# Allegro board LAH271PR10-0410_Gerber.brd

Outline 372.25 x 154.5 mm; copper layers: TOP, GND1, IN1, GND2, IN2, GND3, VCC, IN3, GND4, IN4, GND5, BOTTOM. Coordinates in mm from the lower left corner of the outline.
Outline path: 0,69.3 0,67.85 arc(0.02,67.72) 0.07,67.6 0.43,66.97 arc(0.48,66.85) 0.5,66.72 0.5,59.98 arc(0.48,59.85) 0.43,59.73 0.07,59.1 arc(0.02,58.98) 0,58.85 0,58.05 arc(0.15,57.7) 0.5,57.55 1,57.55 arc(1.5,57.05) 1,56.55 1,53.95 arc(1.5,53.45) 1,52.95 0.5,52.95 arc(0.15,52.8) 0,52.45 0,51.65 arc(0.02,51.52) 0.07,51.4 0.43,50.77 arc(0.48,50.65) 0.5,50.52 0.5,43.78 arc(0.48,43.65) 0.43,43.53 0.07,42.9 arc(0.02,42.78) 0,42.65 0,41.2 1.55,41.2 arc(2.05,40.7) 1.55,40.2 1.55,36.35 1.85,36.35 arc(2.2,36.2) 2.35,35.85 2.35,5.85 arc(2.7,5.7) 2.85,5.35 2.85,0 343.05,0 343.05,5.56 arc(343.42,6.04) 343.98,5.81 arc(344.17,5.62) 344.42,5.56 362.88,5.56 arc(363.13,5.62) 363.32,5.81 arc(363.88,6.04) 364.25,5.56 364.25,0 370.95,0 370.95,1.65 368.9,1.65 arc(367.65,2.9) 368.9,4.15 370.95,4.15 370.95,10.3 arc(371.1,10.65) 371.45,10.8 371.65,10.8 371.65,13.9 371.45,13.9 arc(371.1,14.05) 370.95,14.4 370.95,19.4 arc(371.1,19.75) 371.45,19.9 371.65,19.9 371.65,23 371.45,23 arc(371.1,23.15) 370.95,23.5 370.95,27.8 368.02,27.8 arc(367.52,28.3) 368.02,28.8 368.02,35.8 arc(367.52,36.3) 368.02,36.8 370.95,36.8 370.95,49.8 368.02,49.8 arc(367.52,50.3) 368.02,50.8 368.02,57.8 arc(367.52,58.3) 368.02,58.8 370.95,58.8 370.95,67.5 arc(371.1,67.85) 371.45,68 371.75,68 arc(372.1,68.15) 372.25,68.5 372.25,73.65 arc(372.1,74) 371.75,74.15 361.75,74.15 arc(359.6,73.42) 358.36,71.52 356.68,67.46 354.6,64.28 351.93,61.53 348.42,58.85 arc(338.59,54.15) 327.8,52.7 324.63,52.7 arc(320.32,53.05) 316.08,53.89 arc(308.17,57.19) 301.52,62.6 arc(291.64,77.48) 286.89,94.71 281.32,145.2 274.15,145.2 arc(273.8,145.35) 273.65,145.7 273.65,153 272.15,154.5 241.05,154.5 239.65,153.1 239.65,152.05 arc(239.5,151.7) 239.15,151.55 233.65,151.55 230.7,154.5 217.44,154.5 217.44,144.96 arc(217.3,144.61) 216.94,144.46 215.04,144.46 arc(214.69,144.31) 214.54,143.96 214.54,143.61 arc(214.4,143.26) 214.04,143.11 204.24,143.11 arc(203.89,143.26) 203.74,143.61 203.74,143.96 arc(203.6,144.31) 203.24,144.46 201.34,144.46 arc(200.99,144.61) 200.84,144.96 200.84,154.5 171.45,154.5 171.45,152.05 arc(171.3,151.7) 170.95,151.55 168.45,151.55 168.45,65.5 154.85,51.9 132.4,51.9 arc(132.05,51.75) 131.9,51.4 arc(131.75,51.05) 131.4,50.9 118.15,50.9 arc(117.8,51.05) 117.65,51.4 arc(117.5,51.75) 117.15,51.9 85.45,51.9 arc(85.1,52.05) 84.95,52.4 84.95,64.9 arc(84.66,65.61) 83.95,65.9 75.66,65.9 arc(75.1,65.73) 74.73,65.27 arc(71.94,60.64) 67.78,57.17 arc(66.51,55.89) 66.05,54.15 66.05,43.9 arc(65.9,43.55) 65.55,43.4 48.25,43.4 arc(47.9,43.55) 47.75,43.9 47.75,50.7 arc(47.16,52.11) 45.75,52.7 44.71,52.7 arc(34.33,54.28) 24.88,58.86 21.42,61.5 18.69,64.31 16.55,67.6 14.89,71.71 arc(13.62,73.47) 11.55,74.15 1.55,74.15 1.55,70.3 arc(2.05,69.8) 1.55,69.3 0,69.3

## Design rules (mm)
net group CSS_1: nets CSSN_1 CSSP_1
net group DIFFPAIR127: nets VCC_SA_SENSE VSS_SA_SENSE
net group DIFFPAIR128: nets VCC_SENSE VSS_SENSE
net group DIFFPAIR129: nets VCC_GT_SENSE VSS_GT_SENSE
net group DIFFPAIR130: nets CSSN_2 CSSP_2
net group DIFFPAIR152: nets SW4_DP2_N2 SW4_DP2_P2
net group DIFFPAIR153: nets SW4_DP2_N1 SW4_DP2_P1
net group DIFFPAIR154: nets SW4_DP2_N0 SW4_DP2_P0
net group DIFFPAIR155: nets PCIE_PRX_C_TTX_N4 PCIE_PRX_C_TTX_P4
net group DIFFPAIR156: nets PCIE_PRX_TTX_N4 PCIE_PRX_TTX_P4
net group DIFFPAIR159: nets PCIE_PRX_C_TTX_N3 PCIE_PRX_C_TTX_P3
net group DIFFPAIR160: nets PCIE_PRX_TTX_N3 PCIE_PRX_TTX_P3
net group DIFFPAIR163: nets PCIE_PRX_C_TTX_N2 PCIE_PRX_C_TTX_P2
net group DIFFPAIR164: nets PCIE_PRX_TTX_N2 PCIE_PRX_TTX_P2
net group DIFFPAIR167: nets PCIE_PRX_C_TTX_N1 PCIE_PRX_C_TTX_P1
net group DIFFPAIR168: nets PCIE_PRX_TTX_N1 PCIE_PRX_TTX_P1
net group DIFFPAIR171: nets SW3_DP1_AUXN SW3_DP1_AUXP
net group DIFFPAIR172: nets SW3_DP1_AUXN_C SW3_DP1_AUXP_C
net group DIFFPAIR173: nets SW4_DP2_AUXN SW4_DP2_AUXP
net group DIFFPAIR174: nets SW4_DP2_AUXN_C SW4_DP2_AUXP_C
net group DIFFPAIR175: nets SW3_DP1_N0_C SW3_DP1_P0_C
net group DIFFPAIR176: nets SW3_DP1_N0 SW3_DP1_P0
net group DIFFPAIR177: nets SW3_DP1_N1_C SW3_DP1_P1_C
net group DIFFPAIR178: nets SW3_DP1_N1 SW3_DP1_P1
net group DIFFPAIR179: nets SW3_DP1_N2_C SW3_DP1_P2_C
net group DIFFPAIR180: nets SW3_DP1_N2 SW3_DP1_P2
net group DIFFPAIR181: nets SW3_DP1_N3_C SW3_DP1_P3_C
net group DIFFPAIR182: nets SW3_DP1_N3 SW3_DP1_P3
net group DIFFPAIR191: nets USB20_NB USB20_PB
net group DIFFPAIR192: nets SW4_DP2_N3 SW4_DP2_P3
net group DIFFPAIR224: nets GPU_DP2_N0 GPU_DP2_P0
net group DIFFPAIR225: nets GPU_DP2_N3 GPU_DP2_P3
net group DIFFPAIR226: nets GPU_DP2_N1 GPU_DP2_P1
net group DIFFPAIR227: nets GPU_DP2_N2 GPU_DP2_P2
net group DIFFPAIR238: nets PCH_DPC_CTRL_CLK PCH_DPC_CTRL_DATA
net group DIFFPAIR239: nets SML0_SMBCLK SML0_SMBDATA
net group DIFFPAIR240: nets PCH_CL_CLK1 PCH_CL_DATA1
net group DIFFPAIR245: nets SD_1_CMD_R SD_1_D3_R
net group DIFFPAIR246: nets GPU_SMCLK GPU_SMDAT
net group DIFFPAIR252: nets TBT_B_TRX_DTX_N2_R TBT_B_TRX_DTX_P2_R
net group DIFFPAIR253: nets TBT_B_TRX_DTX_N1_R TBT_B_TRX_DTX_P1_R
net group DIFFPAIR254: nets SW_TBT_A_USB20_N2_R SW_TBT_A_USB20_P2_R
net group DIFFPAIR256: nets TBTA_DPSRC_AUX_N_C TBTA_DPSRC_AUX_P_C
net group DIFFPAIR261: nets TBT_A_TTX_DRX_N1_R TBT_A_TTX_DRX_P1_R
net group DIFFPAIR262: nets TBT_A_TTX_DRX_N2_R TBT_A_TTX_DRX_P2_R
net group DIFFPAIR263: nets TBT_B_TTX_DRX_N1_R TBT_B_TTX_DRX_P1_R
net group DIFFPAIR264: nets DMIC0 DMIC_CLK
net group DIFFPAIR265: nets TBT_B_TTX_DRX_N2_R TBT_B_TTX_DRX_P2_R
net group S18: nets PCH_PECI PECI_EC_R
net group S25: nets VCC_IO_SENSE VSS_IO_SENSE
net group USB3_TX: nets USB3_PRX_L_DTX_N2 USB3_PRX_L_DTX_P2
net group 1111: nets DDR_A_ACT# DDR_A_BA0 DDR_A_BA1 DDR_A_BG0 DDR_A_BG1 DDR_A_CB0 DDR_A_CB1 DDR_A_CB2 DDR_A_CB3 DDR_A_CB4 DDR_A_CB5 DDR_A_CB6 DDR_A_CB7 DDR_A_CKE0 DDR_A_CKE1 DDR_A_CKE2 DDR_A_CKE3 DDR_A_CLK0 DDR_A_CLK1 DDR_A_CLK2 DDR_A_CLK3 DDR_A_CLK#0 DDR_A_CLK#1 DDR_A_CLK#2 DDR_A_CLK#3 DDR_A_CS#0 DDR_A_CS#1 DDR_A_CS#2 DDR_A_CS#3 DDR_A_D0 DDR_A_D1 DDR_A_D2 DDR_A_D3 DDR_A_D4 DDR_A_D5 DDR_A_D6 DDR_A_D7 DDR_A_D8 DDR_A_D9 DDR_A_D10 DDR_A_D11 DDR_A_D12 DDR_A_D13 DDR_A_D14 DDR_A_D15 DDR_A_D16 DDR_A_D17 DDR_A_D18 DDR_A_D19 DDR_A_D20 DDR_A_D21 DDR_A_D22 DDR_A_D23 DDR_A_D24 DDR_A_D25 DDR_A_D26 DDR_A_D27 DDR_A_D28 DDR_A_D29 DDR_A_D30 DDR_A_D31 DDR_A_D32 DDR_A_D33 DDR_A_D34 DDR_A_D35 DDR_A_D36 DDR_A_D37 DDR_A_D38 DDR_A_D39 DDR_A_D40 DDR_A_D41 DDR_A_D42 DDR_A_D43 DDR_A_D44 DDR_A_D45 DDR_A_D46 DDR_A_D47 DDR_A_D48 DDR_A_D49 DDR_A_D50 DDR_A_D51 DDR_A_D52 DDR_A_D53 DDR_A_D54 DDR_A_D55 DDR_A_D56 DDR_A_D57 DDR_A_D58 DDR_A_D59 DDR_A_D60 DDR_A_D61 DDR_A_D62 DDR_A_D63 DDR_A_DQS0 DDR_A_DQS1 DDR_A_DQS2 DDR_A_DQS3 DDR_A_DQS4 DDR_A_DQS5 DDR_A_DQS6 DDR_A_DQS7 DDR_A_DQS8 DDR_A_DQS#0 DDR_A_DQS#1 DDR_A_DQS#2 DDR_A_DQS#3 DDR_A_DQS#4 DDR_A_DQS#5 DDR_A_DQS#6 DDR_A_DQS#7 DDR_A_DQS#8 DDR_A_MA0 DDR_A_MA1 DDR_A_MA2 DDR_A_MA3 DDR_A_MA4 DDR_A_MA5 DDR_A_MA6 DDR_A_MA7 DDR_A_MA8 DDR_A_MA9 DDR_A_MA10 DDR_A_MA11 DDR_A_MA12 DDR_A_MA13 DDR_A_MA14 DDR_A_MA15 DDR_A_MA16 DDR_A_ODT0 DDR_A_ODT1 DDR_A_ODT2 DDR_A_ODT3 DDR_A_PARITY DDR_B_ACT# DDR_B_BA0 DDR_B_BA1 DDR_B_BG0 DDR_B_BG1 DDR_B_CB0 DDR_B_CB1 DDR_B_CB2 DDR_B_CB3 DDR_B_CB4 DDR_B_CB5 DDR_B_CB6 DDR_B_CB7 DDR_B_CKE0 DDR_B_CKE1 DDR_B_CKE2 DDR_B_CKE3 DDR_B_CLK0 DDR_B_CLK1 DDR_B_CLK2 DDR_B_CLK3 DDR_B_CLK#0 DDR_B_CLK#1 DDR_B_CLK#2 DDR_B_CLK#3 DDR_B_CS#0 DDR_B_CS#1 DDR_B_CS#2 DDR_B_CS#3 DDR_B_D0 DDR_B_D1 DDR_B_D2 DDR_B_D3 DDR_B_D4 DDR_B_D5 DDR_B_D6 DDR_B_D7 DDR_B_D8 DDR_B_D9 DDR_B_D10 DDR_B_D11 DDR_B_D12 DDR_B_D13 DDR_B_D14 DDR_B_D15 DDR_B_D16 DDR_B_D17 DDR_B_D18 DDR_B_D19 DDR_B_D20 DDR_B_D21 DDR_B_D22 DDR_B_D23 DDR_B_D24 DDR_B_D25 DDR_B_D26 DDR_B_D27 DDR_B_D28 DDR_B_D29 DDR_B_D30 DDR_B_D31 DDR_B_D32 DDR_B_D33 DDR_B_D34 DDR_B_D35 DDR_B_D36 DDR_B_D37 DDR_B_D38 DDR_B_D39 DDR_B_D40 DDR_B_D41 DDR_B_D42 DDR_B_D43 DDR_B_D44 DDR_B_D45 DDR_B_D46 DDR_B_D47 DDR_B_D48 DDR_B_D49 DDR_B_D50 DDR_B_D51 DDR_B_D52 DDR_B_D53 DDR_B_D54 DDR_B_D55 DDR_B_D56 DDR_B_D57 DDR_B_D58 DDR_B_D59 DDR_B_D60 DDR_B_D61 DDR_B_D62 DDR_B_D63 DDR_B_DQS0 DDR_B_DQS1 DDR_B_DQS2 DDR_B_DQS3 DDR_B_DQS4 DDR_B_DQS5 DDR_B_DQS6 DDR_B_DQS7 DDR_B_DQS8 DDR_B_DQS#0 DDR_B_DQS#1 DDR_B_DQS#2 DDR_B_DQS#3 DDR_B_DQS#4 DDR_B_DQS#5 DDR_B_DQS#6 DDR_B_DQS#7 DDR_B_DQS#8 DDR_B_MA0 DDR_B_MA1 DDR_B_MA2 DDR_B_MA3 DDR_B_MA4 DDR_B_MA5 DDR_B_MA6 DDR_B_MA7 DDR_B_MA8 DDR_B_MA9 DDR_B_MA10 DDR_B_MA11 DDR_B_MA12 DDR_B_MA13 DDR_B_MA14 DDR_B_MA15 DDR_B_MA16 DDR_B_ODT0 DDR_B_ODT1 DDR_B_ODT2 DDR_B_ODT3 DDR_B_PARITY
net group DEMUX-HOU: nets SW1_EDP_AUXN SW1_EDP_AUXN_C SW1_EDP_AUXP SW1_EDP_AUXP_C SW2_DP2_1_AUXN SW2_DP2_1_AUXN_C SW2_DP2_1_AUXP SW2_DP2_1_AUXP_C SW2_DP2_1_N0 SW2_DP2_1_N0_C SW2_DP2_1_N1 SW2_DP2_1_N1_C SW2_DP2_1_N2 SW2_DP2_1_N2_C SW2_DP2_1_N3 SW2_DP2_1_N3_C SW2_DP2_1_P0 SW2_DP2_1_P0_C SW2_DP2_1_P1 SW2_DP2_1_P1_C SW2_DP2_1_P2 SW2_DP2_1_P2_C SW2_DP2_1_P3 SW2_DP2_1_P3_C SW2_DP2_2_AUXN SW2_DP2_2_AUXP SW2_DP2_2_N0 SW2_DP2_2_N1 SW2_DP2_2_N2 SW2_DP2_2_N3 SW2_DP2_2_P0 SW2_DP2_2_P1 SW2_DP2_2_P2 SW2_DP2_2_P3
net group DIFF: nets CLK_PCIE_N1 CLK_PCIE_N2 CLK_PCIE_N3 CLK_PCIE_N4 CLK_PCIE_N6 CLK_PCIE_N7 CLK_PCIE_N8 CLK_PCIE_N9 CLK_PCIE_P1 CLK_PCIE_P2 CLK_PCIE_P3 CLK_PCIE_P4 CLK_PCIE_P6 CLK_PCIE_P7 CLK_PCIE_P8 CLK_PCIE_P9 CLK_PEG_N0 CLK_PEG_P0 CNV_PRX_DTX_N0 CNV_PRX_DTX_N1 CNV_PRX_DTX_P0 CNV_PRX_DTX_P1 CNV_PTX_DRX_N0 CNV_PTX_DRX_N1 CNV_PTX_DRX_P0 CNV_PTX_DRX_P1 CPU_24MHZ_R_D CPU_24MHZ_R_D# CPU_DP1_AUXN CPU_DP1_AUXN_C CPU_DP1_AUXP CPU_DP1_AUXP_C CPU_DP1_N0 CPU_DP1_N0_C CPU_DP1_N1 CPU_DP1_N1_C CPU_DP1_N2 CPU_DP1_N2_C CPU_DP1_N3 CPU_DP1_N3_C CPU_DP1_P0 CPU_DP1_P0_C CPU_DP1_P1 CPU_DP1_P1_C CPU_DP1_P2 CPU_DP1_P2_C CPU_DP1_P3 CPU_DP1_P3_C CPU_DP2_AUXN CPU_DP2_AUXN_C CPU_DP2_AUXP CPU_DP2_AUXP_C CPU_DP2_N0 CPU_DP2_N0_C CPU_DP2_N1 CPU_DP2_N1_C CPU_DP2_N2 CPU_DP2_N2_C CPU_DP2_N3 CPU_DP2_N3_C CPU_DP2_P0 CPU_DP2_P0_C CPU_DP2_P1 CPU_DP2_P1_C CPU_DP2_P2 CPU_DP2_P2_C CPU_DP2_P3 CPU_DP2_P3_C CPU_DP3_AUXN CPU_DP3_AUXP DMI_CRX_PTX_N0 DMI_CRX_PTX_N1 DMI_CRX_PTX_N2 DMI_CRX_PTX_N3 DMI_CRX_PTX_P0 DMI_CRX_PTX_P1 DMI_CRX_PTX_P2 DMI_CRX_PTX_P3 DMI_CTX_PRX_N0 DMI_CTX_PRX_N1 DMI_CTX_PRX_N2 DMI_CTX_PRX_N3 DMI_CTX_PRX_P0 DMI_CTX_PRX_P1 DMI_CTX_PRX_P2 DMI_CTX_PRX_P3 EDP_AUXN EDP_AUXN_C EDP_AUXP EDP_AUXP_C EDP_TXN0 EDP_TXN0_C EDP_TXN1 EDP_TXN1_C EDP_TXN2 EDP_TXN2_C EDP_TXN3 EDP_TXN3_C EDP_TXP0 EDP_TXP0_C EDP_TXP1 EDP_TXP1_C EDP_TXP2 EDP_TXP2_C EDP_TXP3 EDP_TXP3_C LAN_MDIN3 LAN_MDIP3 PCH_CPU_BCLK_D PCH_CPU_BCLK_D# PCH_CPU_BCLK_R_D PCH_CPU_BCLK_R_D# PCH_CPU_NSSC_CLK_D PCH_CPU_NSSC_CLK_D# PCH_CPU_PCIBCLK_D PCH_CPU_PCIBCLK_D# PCH_CPU_PCIBCLK_R_D PCH_CPU_PCIBCLK_R_D# PCIE_PRX_C_DTX_N5 PCIE_PRX_C_DTX_N6 PCIE_PRX_C_DTX_P5 PCIE_PRX_C_DTX_P6 PCIE_PRX_DTX_N5 PCIE_PRX_DTX_N6 PCIE_PRX_DTX_N7 PCIE_PRX_DTX_N8 PCIE_PRX_DTX_N9 PCIE_PRX_DTX_N10 PCIE_PRX_DTX_N11 PCIE_PRX_DTX_N12 PCIE_PRX_DTX_N17 PCIE_PRX_DTX_N18 PCIE_PRX_DTX_N19 PCIE_PRX_DTX_N20 PCIE_PRX_DTX_N21 PCIE_PRX_DTX_N22 PCIE_PRX_DTX_N23 PCIE_PRX_DTX_N24 PCIE_PRX_DTX_P5 PCIE_PRX_DTX_P6 PCIE_PRX_DTX_P7 PCIE_PRX_DTX_P8 PCIE_PRX_DTX_P9 PCIE_PRX_DTX_P10 PCIE_PRX_DTX_P11 PCIE_PRX_DTX_P12 PCIE_PRX_DTX_P17 PCIE_PRX_DTX_P18 PCIE_PRX_DTX_P19 PCIE_PRX_DTX_P20 PCIE_PRX_DTX_P21 PCIE_PRX_DTX_P22 PCIE_PRX_DTX_P23 PCIE_PRX_DTX_P24 PCIE_PTX_C_DRX_N5 PCIE_PTX_C_DRX_N6 PCIE_PTX_C_DRX_N9 PCIE_PTX_C_DRX_N10 PCIE_PTX_C_DRX_N11 PCIE_PTX_C_DRX_N12 PCIE_PTX_C_DRX_N21 PCIE_PTX_C_DRX_N22 PCIE_PTX_C_DRX_N23 PCIE_PTX_C_DRX_N24 PCIE_PTX_C_DRX_P5 PCIE_PTX_C_DRX_P6 PCIE_PTX_C_DRX_P9 PCIE_PTX_C_DRX_P10 PCIE_PTX_C_DRX_P11 PCIE_PTX_C_DRX_P12 PCIE_PTX_C_DRX_P21 PCIE_PTX_C_DRX_P22 PCIE_PTX_C_DRX_P23 PCIE_PTX_C_DRX_P24 PCIE_PTX_DRX_N5 PCIE_PTX_DRX_N6 PCIE_PTX_DRX_N7 PCIE_PTX_DRX_N8 PCIE_PTX_DRX_N9 PCIE_PTX_DRX_N10 PCIE_PTX_DRX_N11 PCIE_PTX_DRX_N12 PCIE_PTX_DRX_N17 PCIE_PTX_DRX_N18 PCIE_PTX_DRX_N19 PCIE_PTX_DRX_N20 PCIE_PTX_DRX_N21 PCIE_PTX_DRX_N22 PCIE_PTX_DRX_N23 PCIE_PTX_DRX_N24 PCIE_PTX_DRX_P5 PCIE_PTX_DRX_P6 PCIE_PTX_DRX_P7 PCIE_PTX_DRX_P8 PCIE_PTX_DRX_P9 PCIE_PTX_DRX_P10 PCIE_PTX_DRX_P11 PCIE_PTX_DRX_P12 PCIE_PTX_DRX_P17 PCIE_PTX_DRX_P18 PCIE_PTX_DRX_P19 PCIE_PTX_DRX_P20 PCIE_PTX_DRX_P21 PCIE_PTX_DRX_P22 PCIE_PTX_DRX_P23 PCIE_PTX_DRX_P24 PEG_CRX_C_GTX_N0 PEG_CRX_C_GTX_N1 PEG_CRX_C_GTX_N2 PEG_CRX_C_GTX_N3 PEG_CRX_C_GTX_N4 PEG_CRX_C_GTX_N5 PEG_CRX_C_GTX_N6 PEG_CRX_C_GTX_N7 PEG_CRX_C_GTX_N8 PEG_CRX_C_GTX_N9 PEG_CRX_C_GTX_N10 PEG_CRX_C_GTX_N11 PEG_CRX_C_GTX_N12 PEG_CRX_C_GTX_N13 PEG_CRX_C_GTX_N14 PEG_CRX_C_GTX_N15 PEG_CRX_C_GTX_P0 PEG_CRX_C_GTX_P1 PEG_CRX_C_GTX_P2 PEG_CRX_C_GTX_P3 PEG_CRX_C_GTX_P4 PEG_CRX_C_GTX_P5 PEG_CRX_C_GTX_P6 PEG_CRX_C_GTX_P7 PEG_CRX_C_GTX_P8 PEG_CRX_C_GTX_P9 PEG_CRX_C_GTX_P10 PEG_CRX_C_GTX_P11 PEG_CRX_C_GTX_P12 PEG_CRX_C_GTX_P13 PEG_CRX_C_GTX_P14 PEG_CRX_C_GTX_P15 PEG_CRX_GTX_N0 PEG_CRX_GTX_N1 PEG_CRX_GTX_N2 PEG_CRX_GTX_N3 PEG_CRX_GTX_N4 PEG_CRX_GTX_N5 PEG_CRX_GTX_N6 PEG_CRX_GTX_N7 PEG_CRX_GTX_N8 PEG_CRX_GTX_N9 PEG_CRX_GTX_N10 PEG_CRX_GTX_N11 PEG_CRX_GTX_N12 PEG_CRX_GTX_N13 PEG_CRX_GTX_N14 PEG_CRX_GTX_N15 PEG_CRX_GTX_P0 PEG_CRX_GTX_P1 PEG_CRX_GTX_P2 PEG_CRX_GTX_P3 PEG_CRX_GTX_P4 PEG_CRX_GTX_P5 PEG_CRX_GTX_P6 PEG_CRX_GTX_P7 PEG_CRX_GTX_P8 PEG_CRX_GTX_P9 PEG_CRX_GTX_P10 PEG_CRX_GTX_P11 PEG_CRX_GTX_P12 PEG_CRX_GTX_P13 PEG_CRX_GTX_P14 PEG_CRX_GTX_P15 PEG_CTX_C_GRX_N1 PEG_CTX_C_GRX_N2 PEG_CTX_C_GRX_N3 PEG_CTX_C_GRX_N4 PEG_CTX_C_GRX_N5 PEG_CTX_C_GRX_N6 PEG_CTX_C_GRX_N7 PEG_CTX_C_GRX_N8 PEG_CTX_C_GRX_N9 PEG_CTX_C_GRX_N10 PEG_CTX_C_GRX_N11 PEG_CTX_C_GRX_N12 PEG_CTX_C_GRX_N13 PEG_CTX_C_GRX_N14 PEG_CTX_C_GRX_N15 PEG_CTX_C_GRX_P0 PEG_CTX_C_GRX_P1 PEG_CTX_C_GRX_P2 PEG_CTX_C_GRX_P3 PEG_CTX_C_GRX_P4 PEG_CTX_C_GRX_P5 PEG_CTX_C_GRX_P6 PEG_CTX_C_GRX_P7 PEG_CTX_C_GRX_P8 PEG_CTX_C_GRX_P9 PEG_CTX_C_GRX_P10 PEG_CTX_C_GRX_P11 PEG_CTX_C_GRX_P12 PEG_CTX_C_GRX_P13 PEG_CTX_C_GRX_P14 PEG_CTX_C_GRX_P15 PEG_CTX_GRX_N0 PEG_CTX_GRX_N1 PEG_CTX_GRX_N2 PEG_CTX_GRX_N3 PEG_CTX_GRX_N4 PEG_CTX_GRX_N5 PEG_CTX_GRX_N6 PEG_CTX_GRX_N7 PEG_CTX_GRX_N8 PEG_CTX_GRX_N9 PEG_CTX_GRX_N10 PEG_CTX_GRX_N11 PEG_CTX_GRX_N12 PEG_CTX_GRX_N13 PEG_CTX_GRX_N14 PEG_CTX_GRX_N15 PEG_CTX_GRX_P0 PEG_CTX_GRX_P1 PEG_CTX_GRX_P2 PEG_CTX_GRX_P3 PEG_CTX_GRX_P4 PEG_CTX_GRX_P5 PEG_CTX_GRX_P6 PEG_CTX_GRX_P7 PEG_CTX_GRX_P8 PEG_CTX_GRX_P9 PEG_CTX_GRX_P10 PEG_CTX_GRX_P11 PEG_CTX_GRX_P12 PEG_CTX_GRX_P13 PEG_CTX_GRX_P14 PEG_CTX_GRX_P15 RJ45_MDIN0 RJ45_MDIN1 RJ45_MDIN2 RJ45_MDIN3 RJ45_MDIP0 RJ45_MDIP1 RJ45_MDIP2 RJ45_MDIP3 SW1_EDP_N0 SW1_EDP_N0_C SW1_EDP_N1 SW1_EDP_N1_C SW1_EDP_N2 SW1_EDP_N2_C SW1_EDP_N3 SW1_EDP_N3_C SW1_EDP_P0 SW1_EDP_P1 SW1_EDP_P1_C SW1_EDP_P2 SW1_EDP_P2_C SW1_EDP_P3 SW1_EDP_P3_C TBT_A_SBU1 TBT_A_SBU2 TBT_B_SBU1 TBT_B_SBU2 TBTA_SBU1 TBTA_SBU2 TBTB_SBU1 TBTB_SBU2 USB3_PRX_DTX_N1 USB3_PRX_DTX_N2 USB3_PRX_DTX_N3 USB3_PRX_DTX_P1 USB3_PRX_DTX_P2 USB3_PRX_DTX_P3 USB3_PTX_DRX_N1 USB3_PTX_DRX_N2 USB3_PTX_DRX_N3 USB3_PTX_DRX_P1 USB3_PTX_DRX_P2 USB3_PTX_DRX_P3 USB20_N1 USB20_N2 USB20_N4 USB20_N5 USB20_N8 USB20_N9 USB20_N9_R USB20_N10 USB20_N11 USB20_N11_R USB20_P1 USB20_P2 USB20_P4 USB20_P5 USB20_P8 USB20_P9 USB20_P9_R USB20_P10 USB20_P11 USB20_P11_R
net group DIFF_CLK: nets PCH_XDP_CLK_DN PCH_XDP_CLK_DN_R PCH_XDP_CLK_DP PCH_XDP_CLK_DP_R
net group DIFFPAIR18: nets PCH_DPD_CTRL_DATA
net group LAN: nets LAN_MDIN0 LAN_MDIN0_L LAN_MDIN1 LAN_MDIN1_L LAN_MDIN2 LAN_MDIN2_L LAN_MDIP0 LAN_MDIP0_L LAN_MDIP1 LAN_MDIP1_L LAN_MDIP2 LAN_MDIP2_L
net group MEM_SMBDATA: nets MEM_SMBDATA
net group MUXPSB331: nets CPU_DP3_N0 CPU_DP3_N1 CPU_DP3_N2 CPU_DP3_N3 CPU_DP3_P0 CPU_DP3_P1 CPU_DP3_P2 CPU_DP3_P3 SW1_EDP_P0_C SW4_DP2_N0_C SW4_DP2_N1_C SW4_DP2_N2_C SW4_DP2_N3_C SW4_DP2_P0_C SW4_DP2_P1_C SW4_DP2_P2_C SW4_DP2_P3_C
net group MXM_DDI: nets GPU_DP1_AUXN GPU_DP1_AUXN_C GPU_DP1_AUXP GPU_DP1_AUXP_C GPU_DP1_N0 GPU_DP1_N0_C GPU_DP1_N1 GPU_DP1_N1_C GPU_DP1_N2 GPU_DP1_N2_C GPU_DP1_N3 GPU_DP1_N3_C GPU_DP1_P0 GPU_DP1_P0_C GPU_DP1_P1 GPU_DP1_P1_C GPU_DP1_P2 GPU_DP1_P2_C GPU_DP1_P3 GPU_DP1_P3_C GPU_DP2_AUXN GPU_DP2_AUXN_C GPU_DP2_AUXP GPU_DP2_AUXP_C GPU_EDP_AUXN GPU_EDP_AUXN_C GPU_EDP_AUXP GPU_EDP_AUXP_C GPU_EDP_N0 GPU_EDP_N0_C GPU_EDP_N1 GPU_EDP_N1_C GPU_EDP_N2 GPU_EDP_N2_C GPU_EDP_N3 GPU_EDP_N3_C GPU_EDP_P0 GPU_EDP_P0_C GPU_EDP_P1 GPU_EDP_P1_C GPU_EDP_P2 GPU_EDP_P2_C GPU_EDP_P3 GPU_EDP_P3_C
net group PCH_DPB_CTRL_DATA: nets PCH_DPB_CTRL_DATA
net group PCIE_RX: nets PCIE_PTX_C_DRX_N7 PCIE_PTX_C_DRX_N8 PCIE_PTX_C_DRX_N17 PCIE_PTX_C_DRX_N18 PCIE_PTX_C_DRX_N19 PCIE_PTX_C_DRX_N20 PCIE_PTX_C_DRX_P7 PCIE_PTX_C_DRX_P8 PCIE_PTX_C_DRX_P17 PCIE_PTX_C_DRX_P18 PCIE_PTX_C_DRX_P19 PCIE_PTX_C_DRX_P20 PCIE_PTX_C_TRX_N1 PCIE_PTX_C_TRX_N2 PCIE_PTX_C_TRX_N3 PCIE_PTX_C_TRX_N4 PCIE_PTX_C_TRX_P1 PCIE_PTX_C_TRX_P2 PCIE_PTX_C_TRX_P3 PCIE_PTX_C_TRX_P4 PCIE_PTX_TRX_N1 PCIE_PTX_TRX_N2 PCIE_PTX_TRX_N3 PCIE_PTX_TRX_N4 PCIE_PTX_TRX_P1 PCIE_PTX_TRX_P2 PCIE_PTX_TRX_P3 PCIE_PTX_TRX_P4
net group REM_DIO: nets REM_DIODE1_N REM_DIODE1_P REM_DIODE2_N REM_DIODE2_P REM_DIODE3_N REM_DIODE3_P REM_DIODE4_N REM_DIODE4_P
net group RTC_SIG: nets PCH_RTCX1 PCH_RTCX1_R PCH_RTCX2 SRTCRST#
net group S12: nets CPU_2_PCH_TRIGGER CPU_2_PCH_TRIGGER_R H_CATERR# H_PM_DOWN H_PM_DOWN_R H_PM_SYNC H_PM_SYNC_R H_PROCHOT#_R H_PWRGD H_THERMTRIP#_R PCH_2_CPU_TRIGGER PCH_2_CPU_TRIGGER_R PCH_THERMTRIP# PCIECOMP PCIECOMP# PROCHOT#_R1 UIM_CLK UIM_DATA VCCST_PWRGD_CPU VCCST_PWRGD_EC XDP_OBS0_R XDP_OBS1_R
net group S15: nets AUD_AZACPU_SCLK AUD_AZACPU_SCLK_R CLKDET# CPU_VIDALERT# CPU_XDP_TCLK GPU_SMBCLK_R HDA_BIT_CLK MEM_SMBCLK PCH_DPB_CTRL_CLK PCH_DPD_CTRL_CLK PCH_DPWROK_EC PCH_SPI_CLK_0_R PCI_CLK_LPC1 PEG_COMP SML1_SMBCLK USB2_COMP VR_SVID_ALERT# VR_SVID_DATA XDP_DBRESET#
net group S20: nets +DDR_VREF_B_DQ +DDR_VREF_CA +DIMM_DQ_R_VREF_B +V_DDR_REFCA_A +V_DDR_REFCA_B CLKREQ_PCIE#10 DDR_A_DRAMRST# DDR_B_DRAMRST# MEC_XTAL1 MEC_XTAL2 XTAL24_IN_R XTAL24_OUT_R1 XTALI XTALO XTALO_R
net group SD: nets SD_1_CLK SD_1_CMD SD_1_D0 SD_1_D0_R SD_1_D1 SD_1_D1_R SD_1_D2 SD_1_D2_R SD_1_D3 SD_1_N0 SD_1_N1 SD_1_P0 SD_1_P1 SDWP_Q
net group SPI: nets PCH_SPI_CLK_2_R PCH_SPI_CS#0 PCH_SPI_CS#0_R1 PCH_SPI_CS#0_R2 PCH_SPI_CS#0_R3 PCH_SPI_CS#1 PCH_SPI_CS#1_R1 PCH_SPI_CS#2 PCH_SPI_CS#2_R PCH_SPI_D0 PCH_SPI_D0_0_R PCH_SPI_D0_1_R PCH_SPI_D0_2_R PCH_SPI_D0_R1 PCH_SPI_D1 PCH_SPI_D1_0_R PCH_SPI_D1_1_R PCH_SPI_D1_2_R PCH_SPI_D1_R1 PCH_SPI_D2 PCH_SPI_D2_0_R PCH_SPI_D2_1_R PCH_SPI_D2_R1 PCH_SPI_D2_XDP PCH_SPI_D3 PCH_SPI_D3_0_R PCH_SPI_D3_1_R PCH_SPI_D3_R1
net group TBT-A: nets TBT_A_TRX_C_DTX_N1 TBT_A_TRX_C_DTX_N2 TBT_A_TRX_C_DTX_P1 TBT_A_TRX_C_DTX_P2 TBT_A_TRX_DTX_N1 TBT_A_TRX_DTX_N1_R TBT_A_TRX_DTX_N2 TBT_A_TRX_DTX_N2_R TBT_A_TRX_DTX_P1 TBT_A_TRX_DTX_P1_R TBT_A_TRX_DTX_P2 TBT_A_TRX_DTX_P2_R TBT_A_TTX_C_DRX_N1 TBT_A_TTX_C_DRX_N2 TBT_A_TTX_C_DRX_P1 TBT_A_TTX_C_DRX_P2 TBT_A_TTX_DRX_N1 TBT_A_TTX_DRX_N2 TBT_A_TTX_DRX_P1 TBT_A_TTX_DRX_P2
net group TBT-ADIFF: nets SW_TBT_A_USB20_N1 SW_TBT_A_USB20_N1_R SW_TBT_A_USB20_N2 SW_TBT_A_USB20_P1 SW_TBT_A_USB20_P1_R SW_TBT_A_USB20_P2 TBT_A_USB20N TBT_A_USB20P USB20_NA USB20_PA
net group TBT-B: nets TBT_B_TRX_C_DTX_N1 TBT_B_TRX_C_DTX_N2 TBT_B_TRX_C_DTX_P1 TBT_B_TRX_C_DTX_P2 TBT_B_TRX_DTX_N1 TBT_B_TRX_DTX_N2 TBT_B_TRX_DTX_P1 TBT_B_TRX_DTX_P2 TBT_B_TTX_C_DRX_N1 TBT_B_TTX_C_DRX_N2 TBT_B_TTX_C_DRX_P1 TBT_B_TTX_C_DRX_P2 TBT_B_TTX_DRX_N1 TBT_B_TTX_DRX_N2 TBT_B_TTX_DRX_P1 TBT_B_TTX_DRX_P2
net group TBT-BDIFF: nets SW_TBT_B_USB20_N1 SW_TBT_B_USB20_N1_R SW_TBT_B_USB20_N2 SW_TBT_B_USB20_N2_R SW_TBT_B_USB20_P1 SW_TBT_B_USB20_P1_R SW_TBT_B_USB20_P2 SW_TBT_B_USB20_P2_R TBT_B_USB20N TBT_B_USB20P TBTB_DPSRC_AUX_N_C TBTB_DPSRC_AUX_P_C
net group USB2: nets CHR_USB20_N1 CHR_USB20_N2 CHR_USB20_P1 CHR_USB20_P2 USB20_N1_R USB20_N2_R USB20_N6 USB20_N14 USB20_N14_R USB20_P1_R USB20_P2_R USB20_P6 USB20_P14 USB20_P14_R
net group USB3_RX: nets USB3_PTX_C_DRX_N1 USB3_PTX_C_DRX_N2 USB3_PTX_C_DRX_N3 USB3_PTX_C_DRX_P1 USB3_PTX_C_DRX_P2 USB3_PTX_C_DRX_P3 USB3_PTX_L_DRX_N2 USB3_PTX_L_DRX_P2
net group W20: nets TBTA_CC1 TBTA_CC2 TBTB_CC1 TBTB_CC2
net group WLAN: nets CLK_CNV_PRX_DTX_N CLK_CNV_PRX_DTX_P CLK_CNV_PTX_DRX_N CLK_CNV_PTX_DRX_N_R CLK_CNV_PTX_DRX_P CLK_CNV_PTX_DRX_P_R CNV_PTX_C_DRX_N0 CNV_PTX_C_DRX_N1 CNV_PTX_C_DRX_P0 CNV_PTX_C_DRX_P1
nets with their own width: min track width 0.254; nets +3.3V_ALW +PWR_SRC_R +RTC_CELL_PCH BATDRV_GATE
nets with their own width: min track width 0.305; nets DDR_RCOMP0 DDR_RCOMP1 DDR_RCOMP2
nets with their own width: min track width 0.381; nets +1.8V_PRIM +3.3V_DGFF LPS_OFF_BATT_R
nets with their own width: min track width 0.508; nets +1.0V_VCCST +1.0V_VCCSTG +3.3V_ALW_PCH +3.3V_ALW_R +3.3V_PGPPG +3.3V_RUN +3.3V_RUN_R_F +5V_HDD +5V_RUN +5V_RUN_PVDD_L +BL_PWR_SRC +CAMERA_VDD_F GND
nets with their own width: min track width 1.524; nets +LCDVDD

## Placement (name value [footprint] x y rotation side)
C190  10U_0402_6.3V6M  [C_0402]  323.01 22.83 180 top
C191  10U_0402_6.3V6M  [C_0402]  202.51 125.33 180 top
C192  470P_0402_50V7K  [C_0402]  325.67 26.81 270 top
C193  470P_0402_50V7K  [C_0402]  324.73 26.81 270 top
C194  10U_0402_6.3V6M  [C_0402]  329.35 20.65 0 top
C195  470P_0402_50V7K  [C_0402]  202.55 126.43 180 top
C200  10U_0402_6.3V6M  [C_0402]  93.45 29.07 270 top
C201  470P_0402_50V7K  [C_0402]  93.05 26.37 180 top
C202  470P_0402_50V7K  [C_0402]  93.05 27.28 180 top
C203  10U_0402_6.3V6M  [C_0402]  92.62 22.55 270 top
C206  10U_0402_6.3V6M  [C_0402]  317.1 16.25 0 top
C207  470P_0402_50V7K  [C_0402]  317.81 14.91 0 top
CA1  220P_0402_50V8J  [C_0402]  350.75 15.24 90 bottom
CA2  680P_0402_50V7K  [C_0402]  355.34 19.6 0 top
CA3  680P_0402_50V7K  [C_0402]  355.39 20.95 0 top
CA4  220P_0402_50V8J  [C_0402]  351.66 15.24 90 bottom
CA8  0.1U_0201_10V6K  [C_0201]  347.27 27.92 0 top
CA9  10U_0603_10V6M  [C_0603]  347.05 29.03 0 top
CA10  0.1U_0201_10V6K  [C_0201]  344.1 18.3 180 top
CA12  680P_0402_50V7K  [C_0402]  353.03 16.07 270 top
CA13  680P_0402_50V7K  [C_0402]  357.88 16.11 270 top
CA19  1000P_0402_50V7K  [C_0402]  321.92 12 0 top
CA22  1000P_0402_50V7K  [C_0402]  320.17 7.81 270 top
CA23  1000P_0402_50V7K  [C_0402]  321.94 9.55 0 top
CA24  1000P_0402_50V7K  [C_0402]  321.9 14.37 0 top
CA25  10U_0603_10V6M  [C_0603]  354.73 24.46 180 top
CA27  0.1U_0201_25V6K  [C_0201]  350.88 27.1 270 bottom
CA28  0.1U_0201_25V6K  [C_0201]  351.79 27.1 270 bottom
CA29  1U_0201_6.3V6K  [C_0201]  349.62 18.63 270 top
CA31  1U_0201_6.3V6M  [C_0201]  337.8 25.39 0 top
CA33  10P_0402_50V8J  [C_0402]  340.45 18.9 180 top
CA35  2.2U_0402_6.3V6M  [C_0402]  348.48 27.31 270 bottom
CA41  0.1U_0201_25V6K  [C_0201]  351.63 16.09 270 top
CA43  10U_0603_10V6M  [C_0603]  350.46 24.96 0 top
CA44  10U_0603_10V6M  [C_0603]  350.45 23.77 0 top
CA45  0.1U_0201_10V6K  [C_0201]  340.22 27.02 180 top
CA46  10U_0603_10V6M  [C_0603]  340.63 27.97 180 top
CA47  0.1U_0201_10V6K  [C_0201]  343.03 30.26 90 top
CA48  10U_0603_10V6M  [C_0603]  340.37 29.29 90 top
CA49  1U_0201_6.3V6K  [C_0201]  351.91 18.99 180 top
CA51  10U_0603_10V6M  [C_0603]  347.27 29.21 270 bottom
CA52  10U_0603_10V6M  [C_0603]  348.22 17.24 90 top
CA53  10U_0603_10V6M  [C_0603]  345.02 16.44 90 top
CA54  68P_0402_50V8J  [C_0402]  340.11 21.38 0 top
CA55  0.1U_0201_10V6K  [C_0201]  345.06 14.02 0 top
CA56  10U_0603_10V6M  [C_0603]  344.37 14.92 0 top
CA57  0.1U_0201_10V6K  [C_0201]  346.28 18.45 0 top
CA58  10U_0603_10V6M  [C_0603]  346.62 17.68 270 top
CA59  10U_0603_10V6M  [C_0603]  341.73 33.44 180 top
CA60  0.1U_0201_10V6K  [C_0201]  341.5 32.5 180 top
CA61  10U_0603_10V6M  [C_0603]  343.7 17.49 270 top
CA63  12P_0402_50V8J  [C_0402]  346.21 34.61 90 top
CA64  68P_0402_50V8J  [C_0402]  345.27 34.61 90 top
CA65  12P_0402_50V8J  [C_0402]  348.34 13.42 0 top
CA66  68P_0402_50V8J  [C_0402]  347.1 14.84 270 top
CA67  12P_0402_50V8J  [C_0402]  343.39 13.97 270 top
CA68  68P_0402_50V8J  [C_0402]  342.48 13.99 270 top
CA69  33P_0402_50V8J  [C_0402]  347.2 16.06 270 bottom
CA73  2P_0402_50V8C  [C_0402]  165.77 42.56 180 top
CA74  2P_0402_50V8C  [C_0402]  163.78 41.09 0 top
CA76  2P_0402_50V8C  [C_0402]  166.44 40.16 180 top
CA224  330P_0402_50V8J  [C_0402]  351.13 21.16 0 bottom
CA225  330P_0402_50V8J  [C_0402]  351.13 20.23 0 bottom
CA226  0.1U_0201_25V6K  [C_0201]  341.81 21.3 0 bottom
CA227  100P_0402_50V8J  [C_0402]  352.97 28.38 0 bottom
CA228  100P_0402_50V8J  [C_0402]  351.07 28.29 0 bottom
CA232  1U_0201_6.3V6K  [C_0201]  350.2 18.63 270 top
CA233  1U_0201_6.3V6K  [C_0201]  351.91 19.59 180 top
CC28  0.1U_0402_25V6  [C_0402]  278.84 91.5 270 top
CC29  0.1U_0402_25V6  [C_0402]  277.95 91.5 270 top
CC32  0.1U_0402_25V6  [C_0402]  278.17 93.72 0 top
CC33  0.1U_0402_25V6  [C_0402]  279.08 84.74 90 bottom
CC34  0.22U_0402_16V7K  [C_0402]  209.71 111.1 180 top
CC35  0.22U_0402_16V7K  [C_0402]  209.71 111.99 180 top
CC36  0.22U_0402_16V7K  [C_0402]  207.16 110.78 180 top
CC37  0.22U_0402_16V7K  [C_0402]  207.16 109.89 180 top
CC38  0.22U_0402_16V7K  [C_0402]  209.72 108.62 180 top
CC39  0.22U_0402_16V7K  [C_0402]  209.72 109.51 180 top
CC40  0.22U_0402_16V7K  [C_0402]  207.16 108.4 180 top
CC41  0.22U_0402_16V7K  [C_0402]  207.16 107.51 180 top
CC42  0.22U_0402_16V7K  [C_0402]  209.72 106 180 top
CC43  0.22U_0402_16V7K  [C_0402]  209.72 106.89 180 top
CC44  0.22U_0402_16V7K  [C_0402]  207.17 106.04 180 top
CC45  0.22U_0402_16V7K  [C_0402]  207.17 105.15 180 top
CC46  0.22U_0402_16V7K  [C_0402]  209.7 103.79 180 top
CC47  0.22U_0402_16V7K  [C_0402]  209.7 104.68 180 top
CC48  0.22U_0402_16V7K  [C_0402]  207.15 103.61 180 top
CC49  0.22U_0402_16V7K  [C_0402]  207.15 102.72 180 top
CC50  0.22U_0402_16V7K  [C_0402]  209.67 102.21 180 top
CC51  0.22U_0402_16V7K  [C_0402]  209.67 101.32 180 top
CC52  0.22U_0402_16V7K  [C_0402]  207.17 100.34 180 top
CC53  0.22U_0402_16V7K  [C_0402]  207.17 101.23 180 top
CC54  0.22U_0402_16V7K  [C_0402]  209.7 99.84 180 top
CC55  0.22U_0402_16V7K  [C_0402]  209.7 98.95 180 top
CC56  0.22U_0402_16V7K  [C_0402]  207.15 97.96 180 top
CC57  0.22U_0402_16V7K  [C_0402]  207.15 98.85 180 top
CC58  0.22U_0402_16V7K  [C_0402]  209.7 97.39 180 top
CC59  0.22U_0402_16V7K  [C_0402]  209.7 96.5 180 top
CC60  0.22U_0402_16V7K  [C_0402]  207.15 95.59 180 top
CC61  0.22U_0402_16V7K  [C_0402]  207.15 96.48 180 top
CC62  0.22U_0402_16V7K  [C_0402]  209.7 94.86 180 top
CC63  0.22U_0402_16V7K  [C_0402]  209.7 93.98 180 top
CC64  0.22U_0402_16V7K  [C_0402]  209.67 91.95 180 top
CC65  0.22U_0402_16V7K  [C_0402]  209.67 92.83 180 top
CC81  22U_0603_6.3V6M  [C_0603]  257.77 87.3 180 bottom
CC82  22U_0603_6.3V6M  [C_0603]  243.93 87.28 180 bottom
CC83  22U_0603_6.3V6M  [C_0603]  223.47 87.29 180 bottom
CC84  22U_0603_6.3V6M  [C_0603]  254.84 87.29 180 bottom
CC161  10U_0402_6.3V6M  [C_0402]  231.19 87.36 180 bottom
CC163  10U_0402_6.3V6M  [C_0402]  228.71 87.34 180 bottom
CC164  10U_0402_6.3V6M  [C_0402]  286.09 72.06 270 top
CC165  10U_0402_6.3V6M  [C_0402]  233.62 87.42 180 bottom
CC166  10U_0402_6.3V6M  [C_0402]  248.81 87.32 180 bottom
CC167  10U_0402_6.3V6M  [C_0402]  235.76 87.31 180 bottom
CC168  10U_0402_6.3V6M  [C_0402]  238.29 87.35 180 bottom
CC170  10U_0402_6.3V6M  [C_0402]  240.75 87.33 180 bottom
CC171  10U_0402_6.3V6M  [C_0402]  251.32 87.34 180 bottom
CC172  10U_0402_6.3V6M  [C_0402]  246.33 87.33 180 bottom
CC185  10U_0402_6.3V6M  [C_0402]  201.54 68.84 90 bottom
CC186  1U_0201_6.3V6M  [C_0201]  223.65 106.19 90 bottom
CC187  10U_0603_6.3V6M  [C_0603]  223.54 98.75 270 bottom
CC188  10U_0603_6.3V6M  [C_0603]  223.64 99.83 0 bottom
CC189  10U_0603_6.3V6M  [C_0603]  223.65 101.03 0 bottom
CC191  1U_0201_6.3V6M  [C_0201]  222.12 108.09 90 bottom
CC192  1U_0201_6.3V6M  [C_0201]  224.31 105.56 90 bottom
CC193  1U_0201_10V6M  [C_0201]  209.59 106.79 0 bottom
CC194  1U_0201_10V6M  [C_0201]  209.59 107.65 0 bottom
CC195  1U_0201_6.3V6M  [C_0201]  223.08 106.17 90 bottom
CC209  1U_0201_6.3V6M  [C_0201]  263.39 95.62 180 top
CC210  1U_0201_6.3V6M  [C_0201]  263.39 95.04 180 top
CC269  0.1U_0402_25V6  [C_0402]  279.42 90.5 180 bottom
CC272  10U_0603_6.3V6M  [C_0603]  223.64 102.24 0 bottom
CC300  100P_0402_50V8J  [C_0402]  265.32 108.69 0 top
CC301  100P_0402_50V8J  [C_0402]  196.64 92.74 180 bottom
CC302  0.1U_0201_25V6K  [C_0201]  177.14 46.54 0 top
CC303  0.1U_0201_25V6K  [C_0201]  275.2 95.29 180 top
CC304  0.1U_0201_25V6K  [C_0201]  278.53 96.56 0 top
CC305  0.1U_0201_25V6K  [C_0201]  284.01 101.67 90 top
CC306  0.1U_0402_25V6  [C_0402]  278.17 94.64 0 top
CC307  0.1U_0402_25V6  [C_0402]  279.51 87.84 180 bottom
CC308  0.1U_0402_25V6  [C_0402]  276.91 97.16 180 top
CC310  0.1U_0201_10V6K  [C_0201]  167.46 36.76 0 bottom
CC311  0.1U_0201_10V6K  [C_0201]  198.46 46.89 0 top
CC318  33P_0402_50V8J  [C_0402]  168.26 31.42 0 top
CC319  33P_0402_50V8J  [C_0402]  167.54 30.22 0 bottom
CC320  33P_0402_50V8J  [C_0402]  163.64 29.95 270 top
CC322  2.2P_0402_50V8C  [C_0402]  276.37 85.83 0 top
CC323  0.1U_0402_25V6  [C_0402]  198.91 116.74 0 bottom
CC324  0.1U_0402_25V6  [C_0402]  267.28 107 0 top
CC325  33P_0402_50V8J  [C_0402]  260.06 119.16 90 bottom
CC327  2.2P_0402_50V8C  [C_0402]  167.2 39.27 0 bottom
CC328  2.2P_0402_50V8C  [C_0402]  189.6 26.93 180 bottom
CC329  0.1U_0201_10V6K  [C_0201]  168.22 38.49 180 bottom
CC330  0.1U_0201_10V6K  [C_0201]  199.4 49.88 0 top
CC331  0.1U_0201_10V6K  [C_0201]  197.89 44.09 270 bottom
CC332  0.1U_0201_10V6K  [C_0201]  199.16 42.57 0 bottom
CC333  22U_0603_6.3V6M  [C_0603]  210.09 109.96 270 bottom
CC334  0.1U_0402_25V6  [C_0402]  262.8 94.3 0 top
CC335  22U_0603_6.3V6M  [C_0603]  208.82 108.56 90 bottom
CC336  0.1U_0402_25V6  [C_0402]  278.5 97.3 0 top
CC337  0.1U_0402_25V6  [C_0402]  281.71 77.72 270 bottom
CC338  0.1U_0402_25V6  [C_0402]  282.65 76.81 90 bottom
CC568  22U_0603_6.3V6M  [C_0603]  267.71 98.95 180 bottom
CC569  22U_0603_6.3V6M  [C_0603]  202.29 113.73 270 bottom
CD1  1U_0201_10V6M  [C_0201]  202.49 30.7 180 bottom
CD2  1U_0201_10V6M  [C_0201]  202.45 31.61 180 bottom
CD3  10U_0603_6.3V6M  [C_0603]  201.87 33.32 180 bottom
CD4  10U_0603_6.3V6M  [C_0603]  201.87 34.53 180 bottom
CD5  0.1U_0402_10V6K  [C_0402]  250.52 66.51 180 bottom
CD6  10U_0603_6.3V6M  [C_0603]  268.67 32.92 0 bottom
CD7  10U_0603_6.3V6M  [C_0603]  259.68 32.66 0 bottom
CD8  10U_0603_6.3V6M  [C_0603]  259.68 33.93 0 bottom
CD9  10U_0603_6.3V6M  [C_0603]  257.01 31.82 180 bottom
CD10  10U_0603_6.3V6M  [C_0603]  266.51 31.58 180 bottom
CD11  10U_0603_6.3V6M  [C_0603]  245.71 29.48 0 bottom
CD12  10U_0603_6.3V6M  [C_0603]  257.03 30.52 180 bottom
CD13  10U_0603_6.3V6M  [C_0603]  268.67 34.19 0 bottom
CD14  330U_D2_2V_Y  [C_D2]  200.22 72.55 90 top
CD15  0.1U_0201_10V6K  [C_0201]  249.67 63.3 90 bottom
CD16  0.1U_0402_10V6K  [C_0402]  256.7 34.21 180 bottom
CD17  1U_0201_10V6M  [C_0201]  251.26 34.01 0 bottom
CD18  1U_0201_10V6M  [C_0201]  245.8 32.47 0 bottom
CD19  1U_0201_10V6M  [C_0201]  266.38 32.81 180 bottom
CD20  1U_0201_10V6M  [C_0201]  244.81 31.22 180 bottom
CD21  1U_0201_10V6M  [C_0201]  244.81 32.98 180 bottom
CD22  1U_0201_10V6M  [C_0201]  244.81 32.1 180 bottom
CD23  1U_0201_10V6M  [C_0201]  245.96 30.56 0 bottom
CD24  1U_0201_10V6M  [C_0201]  256.45 32.99 180 bottom
CD25  0.022U_0402_16V7K  [C_0402]  234.37 31.71 0 bottom
CD26  0.1U_0402_10V6K  [C_0402]  231.73 33.49 180 bottom
CD27  10U_0603_6.3V6M  [C_0603]  201.55 46.77 180 bottom
CD28  0.1U_0402_10V6K  [C_0402]  231.73 29.04 180 bottom
CD29  2.2U_0402_6.3V6M  [C_0402]  231.73 29.93 180 bottom
CD30  1U_0201_10V6M  [C_0201]  209.49 64.09 0 bottom
CD31  1U_0201_10V6M  [C_0201]  207.19 49.17 270 top
CD32  0.1U_0402_10V6K  [C_0402]  210.9 34.18 180 bottom
CD33  2.2U_0603_10V7K  [C_0603]  211.79 34.03 0 bottom
CD34  0.1U_0402_25V6  [C_0402]  285.71 71.83 270 bottom
CD35  10U_0603_6.3V6M  [C_0603]  202.54 55.14 180 top
CD36  1U_0201_10V6M  [C_0201]  211.82 30.15 0 bottom
CD37  1U_0201_10V6M  [C_0201]  211.84 29.27 0 bottom
CD38  10U_0603_6.3V6M  [C_0603]  202.54 56.34 180 top
CD39  10U_0603_6.3V6M  [C_0603]  251.15 31.58 0 bottom
CD40  10U_0603_6.3V6M  [C_0603]  244.92 34.14 180 bottom
CD41  10U_0603_6.3V6M  [C_0603]  239.34 33.05 0 bottom
CD42  10U_0603_6.3V6M  [C_0603]  251.15 32.85 0 bottom
CD43  10U_0603_6.3V6M  [C_0603]  244.68 30.17 180 bottom
CD44  10U_0603_6.3V6M  [C_0603]  223.17 34.35 180 bottom
CD45  10U_0603_6.3V6M  [C_0603]  239.34 34.34 0 bottom
CD46  10U_0603_6.3V6M  [C_0603]  251.15 30.31 0 bottom
CD47  330U_D2_2V_Y  [C_D2]  198.36 66.89 90 bottom
CD48  0.1U_0201_10V6K  [C_0201]  250.63 63.21 0 bottom
CD49  1U_0201_10V6M  [C_0201]  224.97 33.88 0 bottom
CD50  1U_0201_10V6M  [C_0201]  224.97 32.99 0 bottom
CD51  1U_0201_10V6M  [C_0201]  245.8 31.46 0 bottom
CD52  1U_0201_10V6M  [C_0201]  222.78 33.22 180 bottom
CD53  1U_0201_10V6M  [C_0201]  214.06 33.95 0 bottom
CD54  1U_0201_10V6M  [C_0201]  239.68 31.93 0 bottom
CD55  1U_0201_10V6M  [C_0201]  245.82 33.96 0 bottom
CD56  1U_0201_10V6M  [C_0201]  237.2 32.64 270 bottom
CD57  10U_0603_6.3V6M  [C_0603]  201.46 38.15 180 bottom
CD58  1U_0201_10V6M  [C_0201]  201.29 39.17 180 bottom
CD59  1U_0201_10V6M  [C_0201]  201.29 40.08 180 bottom
CD60  0.1U_0402_10V6K  [C_0402]  231.73 31.71 180 bottom
CD61  2.2U_0402_6.3V6M  [C_0402]  231.73 32.6 180 bottom
CD62  0.1U_0402_10V6K  [C_0402]  202.45 43.29 180 bottom
CD63  2.2U_0603_10V7K  [C_0603]  202.59 44.34 180 bottom
CD64  1U_0201_10V6M  [C_0201]  211.85 31.94 0 bottom
CD65  1U_0201_10V6M  [C_0201]  211.85 31.04 0 bottom
CD66  10U_0603_6.3V6M  [C_0603]  202.33 50.3 180 top
CD67  10U_0603_6.3V6M  [C_0603]  201.25 53.92 180 top
CD68  10U_0603_6.3V6M  [C_0603]  216.37 33.33 270 bottom
CD69  10U_0603_6.3V6M  [C_0603]  230.13 63.4 90 bottom
CD70  10U_0603_6.3V6M  [C_0603]  226.95 63.4 90 bottom
CD71  10U_0603_6.3V6M  [C_0603]  239.34 66.25 180 bottom
CD72  10U_0603_6.3V6M  [C_0603]  218.7 63.9 90 bottom
CD73  10U_0603_6.3V6M  [C_0603]  239.35 30.87 0 bottom
CD74  10U_0603_6.3V6M  [C_0603]  241.05 63.14 90 bottom
CD75  10U_0603_6.3V6M  [C_0603]  220.98 63.9 90 bottom
CD76  330U_D2_2V_Y  [C_D2]  200.06 62.28 90 top
CD77  0.1U_0402_10V6K  [C_0402]  271.44 78.46 180 bottom
CD78  0.1U_0201_10V6K  [C_0201]  248.67 65.54 90 bottom
CD79  1U_0201_10V6M  [C_0201]  239.35 65.11 180 bottom
CD80  1U_0201_10V6M  [C_0201]  219.84 64.4 90 bottom
CD81  1U_0201_10V6M  [C_0201]  215.25 33.18 270 bottom
CD82  1U_0201_10V6M  [C_0201]  228.1 63.89 90 bottom
CD83  1U_0201_10V6M  [C_0201]  228.99 63.89 90 bottom
CD84  1U_0201_10V6M  [C_0201]  239.35 63.08 180 bottom
CD85  1U_0201_10V6M  [C_0201]  236.41 34.66 90 bottom
CD86  1U_0201_10V6M  [C_0201]  262.23 63.3 90 bottom
CD87  0.022U_0402_16V7K  [C_0402]  272.38 83.88 270 bottom
CD88  0.1U_0402_10V6K  [C_0402]  270.52 82.91 0 bottom
CD89  0.1U_0402_10V6K  [C_0402]  270.52 82.02 0 bottom
CD90  0.1U_0402_10V6K  [C_0402]  270.52 80.24 0 bottom
CD91  10U_0603_6.3V6M  [C_0603]  201.54 49.23 180 bottom
CD92  1U_0201_10V6M  [C_0201]  201.56 50.42 180 bottom
CD93  1U_0201_10V6M  [C_0201]  209.49 63.21 0 bottom
CD94  0.1U_0402_10V6K  [C_0402]  232.74 65.24 180 bottom
CD95  2.2U_0402_6.3V6M  [C_0402]  232.74 64.22 180 bottom
CD96  0.1U_0402_10V6K  [C_0402]  239.35 64.09 180 bottom
CD97  0.1U_0402_10V6K  [C_0402]  232.74 63.21 180 bottom
CD98  0.1U_0402_10V6K  [C_0402]  196.68 57.31 180 bottom
CD99  2.2U_0603_10V7K  [C_0603]  196.7 56.25 180 bottom
CD100  1U_0201_10V6M  [C_0201]  211.84 28.23 0 bottom
CD101  1U_0201_10V6M  [C_0201]  211.84 27.31 0 bottom
CD102  10U_0603_6.3V6M  [C_0603]  202.33 52.71 180 top
CD103  10U_0603_6.3V6M  [C_0603]  202.31 51.51 180 top
CD104  10U_0603_6.3V6M  [C_0603]  247.46 66.51 180 bottom
CD105  10U_0603_6.3V6M  [C_0603]  272.31 62.92 90 bottom
CD106  10U_0603_6.3V6M  [C_0603]  261.12 63.27 90 bottom
CD107  10U_0603_6.3V6M  [C_0603]  247.46 65.3 180 bottom
CD108  10U_0603_6.3V6M  [C_0603]  252.61 63.4 90 bottom
CD109  10U_0603_6.3V6M  [C_0603]  244.69 28.9 180 bottom
CD110  10U_0603_6.3V6M  [C_0603]  244.85 65.64 180 bottom
CD111  10U_0603_6.3V6M  [C_0603]  244.85 64.44 180 bottom
CD112  330U_D2_2V_Y  [C_D2]  283.21 75.14 270 top
CD113  0.1U_0201_10V6K  [C_0201]  248.67 63.26 90 bottom
CD114  1U_0201_10V6M  [C_0201]  222.71 31.78 180 bottom
CD115  1U_0201_10V6M  [C_0201]  239.79 29.74 0 bottom
CD116  1U_0201_10V6M  [C_0201]  239.79 28.81 0 bottom
CD117  1U_0201_10V6M  [C_0201]  253.75 63.38 90 bottom
CD118  1U_0201_10V6M  [C_0201]  259.95 31.58 0 bottom
CD119  1U_0201_10V6M  [C_0201]  244.91 63.21 0 bottom
CD120  1U_0201_10V6M  [C_0201]  247.6 64.22 180 bottom
CD121  1U_0201_10V6M  [C_0201]  247.6 63.21 180 bottom
CD122  10U_0603_6.3V6M  [C_0603]  201.55 47.98 180 bottom
CD123  1U_0201_10V6M  [C_0201]  210.04 34.54 180 top
CD124  1U_0201_10V6M  [C_0201]  201.56 51.31 180 bottom
CD125  0.1U_0402_10V6K  [C_0402]  233.78 65.29 0 bottom
CD126  2.2U_0402_6.3V6M  [C_0402]  233.79 66.21 0 bottom
CD127  0.1U_0402_10V6K  [C_0402]  202.4 58.6 180 top
CD128  2.2U_0603_10V7K  [C_0603]  202.58 59.64 180 top
CE3  2200P_0402_50V7K  [C_0402]  131.19 13.97 270 bottom
CE4  2200P_0402_50V7K  [C_0402]  132.25 17.38 180 bottom
CE8  0.047U_0201_10V6K  [C_0201]  137.67 17.57 0 top
CE10  1U_0201_10V6M  [C_0201]  128.45 39.02 270 bottom
CE11  0.1U_0201_10V6K  [C_0201]  131.71 31.44 90 top
CE12  2.2U_0402_6.3V6M  [C_0402]  131.14 38.1 90 bottom
CE13  0.1U_0201_10V6K  [C_0201]  127.84 24.03 180 top
CE14  1U_0201_10V6M  [C_0201]  142.64 19.84 180 top
CE15  0.1U_0201_10V6K  [C_0201]  135.08 25.49 90 bottom
CE16  10U_0402_6.3V6M  [C_0402]  146.19 19.22 0 top
CE17  22U_0603_6.3V6M  [C_0603]  126.83 27.47 270 top
CE18  0.1U_0201_10V6K  [C_0201]  127.8 26.61 270 top
CE19  0.1U_0201_10V6K  [C_0201]  137.18 19.45 270 bottom
CE20  0.1U_0201_10V6K  [C_0201]  129.84 20.6 180 bottom
CE21  0.1U_0201_10V6K  [C_0201]  133.44 17.07 270 top
CE22  0.1U_0201_10V6K  [C_0201]  132.74 12.98 0 top
CE23  0.1U_0201_10V6K  [C_0201]  135.01 30.32 90 bottom
CE24  2200P_0402_50V7K  [C_0402]  135.76 31.47 180 top
CE25  0.1U_0201_10V6K  [C_0201]  139.09 22.83 0 bottom
CE26  2200P_0402_50V7K  [C_0402]  137.58 32.24 180 top
CE27  2200P_0402_50V7K  [C_0402]  139.33 31.79 180 top
CE28  10P_0402_50V8J  [C_0402]  132.51 34.1 180 top
CE29  12P_0402_50V8J  [C_0402]  133.77 34.05 0 top
CE30  1U_0201_10V6M  [C_0201]  146.09 28.27 270 top
CE31  1U_0201_10V6M  [C_0201]  127.52 22.06 180 top
CE35  100P_0402_50V8J  [C_0402]  245.73 99.99 180 bottom
CE36  0.1U_0201_25V6K  [C_0201]  155.54 29.54 90 top
CE38  0.1U_0201_25V6K  [C_0201]  136.78 30.34 0 bottom
CE39  100P_0402_50V8J  [C_0402]  278.3 14.7 270 top
CE40  4700P_0402_25V7K  [C_0402]  141.89 24.51 0 top
CE46  100P_0402_50V8J  [C_0402]  68.44 41.31 0 bottom
CE47  4700P_0402_25V7K  [C_0402]  139.09 21.71 0 bottom
CE52  0.1U_0201_25V6K  [C_0201]  161.53 22.92 180 top
CE53  0.1U_0201_25V6K  [C_0201]  156.65 17.86 90 top
CE54  10P_0402_50V8J  [C_0402]  129.42 25.95 180 bottom
CE57  33P_0402_50V8J  [C_0402]  135.19 23.32 90 bottom
CE59  12P_0402_50V8J  [C_0402]  130.75 12.96 0 top
CE60  68P_0402_50V8J  [C_0402]  129.42 12.88 180 top
CE61  68P_0402_50V8J  [C_0402]  157.14 22.47 270 top
CE62  4700P_0402_25V7K  [C_0402]  120 26.89 0 bottom
CE63  1U_0201_10V6M  [C_0201]  154.5 29.95 90 top
CE64  0.1U_0201_25V6K  [C_0201]  153.56 31.9 0 top
CE65  22P_0402_50V8J  [C_0402]  148.95 28.8 180 top
CE66  0.1U_0201_25V6K  [C_0201]  135.3 14.94 180 bottom
CE270  2200P_0402_50V7K  [C_0402]  135.92 29.52 180 bottom
CE272  100P_0402_50V8J  [C_0402]  198.48 57.09 180 top
CE339  100P_0402_50V8J  [C_0402]  251.17 151.35 180 top
CE340  0.1U_0201_25V6K  [C_0201]  7.2 9.71 270 bottom
CE341  0.1U_0201_25V6K  [C_0201]  9.87 17.63 270 bottom
CE342  0.1U_0201_25V6K  [C_0201]  11.54 9.48 270 bottom
CE343  1U_0201_10V6M  [C_0201]  5.93 13.73 90 bottom
CH4  18P_0402_50V8J  [C_0402]  170.83 15.36 270 top
CH5  18P_0402_50V8J  [C_0402]  169.74 15.34 270 top
CH9  0.1U_0201_10V6K  [C_0201]  137.44 41.47 90 bottom
CH10  0.1U_0201_25V6K  [C_0201]  173.53 50.81 270 top
CH13  15P_0402_50V8J  [C_0402]  191.06 49.96 0 top
CH14  15P_0402_50V8J  [C_0402]  190.16 49.58 180 top
CH20  1U_0201_6.3V6M  [C_0201]  197.33 44.09 270 bottom
CH21  1U_0201_6.3V6M  [C_0201]  173.94 37.52 0 bottom
CH22  4.7U_0402_6.3V6M  [C_0402]  173.79 36.63 0 bottom
CH29  1U_0201_6.3V6M  [C_0201]  195.51 51.79 90 bottom
CH30  4.7U_0402_6.3V6M  [C_0402]  168.93 44.34 180 top
CH31  1U_0201_6.3V6M  [C_0201]  198.83 47.83 0 top
CH32  4.7U_0402_6.3V6M  [C_0402]  197.16 45.11 0 bottom
CH33  1U_0201_6.3V6M  [C_0201]  172.52 16.58 270 bottom
CH34  1U_0201_6.3V6M  [C_0201]  196.88 31.82 90 bottom
CH35  1U_0201_6.3V6M  [C_0201]  169.4 20.41 180 top
CH36  1U_0201_6.3V6M  [C_0201]  183.04 28.34 270 bottom
CH37  1U_0201_6.3V6M  [C_0201]  172.73 42.12 135 bottom
CH38  0.1U_0201_10V6K  [C_0201]  194.86 36.28 0 bottom
CH40  1U_0201_6.3V6M  [C_0201]  164.66 17.39 0 top
CH41  1U_0201_6.3V6M  [C_0201]  174.72 17.02 0 bottom
CH44  0.1U_0201_10V6K  [C_0201]  192.17 37.43 90 bottom
CH45  47U_0603_6.3V6M  [C_0603]  195.88 56.82 270 top
CH46  1U_0201_6.3V6M  [C_0201]  197.16 46 0 bottom
CH47  22U_0603_6.3V6M  [C_0603]  195.95 31.3 90 bottom
CH62  0.1U_0201_10V6K  [C_0201]  183.27 26.11 90 bottom
CH63  0.1U_0201_10V6K  [C_0201]  169.14 18.24 90 top
CH64  0.1U_0201_10V6K  [C_0201]  186.72 25.99 90 bottom
CH65  0.1U_0201_10V6K  [C_0201]  171.59 17.13 270 bottom
CH66  0.1U_0201_10V6K  [C_0201]  189.66 19.96 180 bottom
CH67  0.1U_0201_10V6K  [C_0201]  168.46 43.56 90 bottom
CH68  0.1U_0201_10V6K  [C_0201]  169.93 19.37 270 top
CH266  0.01U_0402_16V7K  [C_0402]  172.79 19.09 270 bottom
CH267  1U_0201_6.3V6M  [C_0201]  198.23 16.2 270 top
CH268  47P_0402_50V8J  [C_0402]  165.52 41.09 0 top
CH270  0.1U_0201_10V6K  [C_0201]  116.26 29.48 180 top
CH321  33P_0402_50V8J  [C_0402]  115.33 33.87 0 top
CH322  33P_0402_50V8J  [C_0402]  138.5 44.82 90 bottom
CH323  4.7U_0402_6.3V6M  [C_0402]  169.39 43.4 90 bottom
CH324  22U_0603_6.3V6M  [C_0603]  199.86 18.48 90 top
CH340  0.1U_0201_25V6K  [C_0201]  123.13 10.06 270 top
CH341  0.033U_0402_16V7  [C_0402]  154.66 32.77 0 top
CH342  0.033U_0402_16V7  [C_0402]  279.45 84.37 0 top
CH343  0.033U_0402_16V7  [C_0402]  140.73 18.69 270 bottom
CH344  0.033U_0402_16V7  [C_0402]  152.57 36.07 90 top
CH345  0.033U_0402_16V7  [C_0402]  133.85 13.61 180 bottom
CH346  0.033U_0402_16V7  [C_0402]  208.04 125.45 0 top
CH347  0.033U_0402_16V7  [C_0402]  135.27 16.26 180 bottom
CH348  0.033U_0402_16V7  [C_0402]  161.33 19.4 0 bottom
CH349  0.047U_0201_10V6K  [C_0201]  156.47 33.21 270 bottom
CH350  0.047U_0201_10V6K  [C_0201]  44.95 37.44 180 bottom
CH555  1U_0201_6.3V6M  [C_0201]  198.8 16.2 270 top
CH559  4.7U_0402_6.3V6M  [C_0402]  168.18 45.8 180 top
CH560  22U_0603_6.3V6M  [C_0603]  200.41 16.78 0 top
CI1  150U_B2_6.3VM_R35M  [C_B2]  351.53 33.49 0 top
CI3  10U_0402_6.3V6M  [C_0402]  356.81 28.77 90 top
CI13  0.1U_0201_10V6K  [C_0201]  353.58 53.21 180 bottom
CI14  10U_0402_6.3V6M  [C_0402]  356.77 48.82 270 top
CI16  0.1U_0201_10V6K  [C_0201]  353.56 54.09 180 bottom
CI32  150U_B2_6.3VM_R35M  [C_B2]  354.63 49.57 90 top
CI63  0.1U_0201_10V6K  [C_0201]  354.5 31.84 180 top
CI65  0.1U_0201_10V6K  [C_0201]  354.5 32.76 180 top
CL1  0.1U_0201_10V6K  [C_0201]  195.24 124.84 0 bottom
CL2  0.1U_0201_10V6K  [C_0201]  195.24 123.82 0 bottom
CL3  10U_0402_6.3V6M  [C_0402]  185.12 123.26 180 bottom
CL4  0.1U_0201_10V6K  [C_0201]  191.09 130.16 270 top
CL5  0.1U_0201_10V6K  [C_0201]  197.02 118.1 90 bottom
CL6  0.1U_0201_10V6K  [C_0201]  196.13 118.1 90 bottom
CL7  1U_0201_10V6M  [C_0201]  185.12 125.05 270 bottom
CL8  22U_0603_6.3V6M  [C_0603]  180.69 125.28 270 bottom
CL9  0.1U_0201_10V6K  [C_0201]  187.06 128.17 0 top
CL10  0.1U_0201_10V6K  [C_0201]  188.81 130.16 270 top
CL11  0.1U_0201_10V6K  [C_0201]  187.06 129.39 0 top
CL12  0.1U_0201_10V6K  [C_0201]  187.99 122.73 270 bottom
CL13  27P_0402_50V8J  [C_0402]  183.99 129.8 270 bottom
CL14  27P_0402_50V8J  [C_0402]  183.99 130.66 90 bottom
CL15  0.1U_0201_10V6K  [C_0201]  195.49 134.81 90 top
CL16  0.47U_0201_25V6M  [C_0201]  183.07 139.14 270 top
CL17  0.47U_0201_25V6M  [C_0201]  184.31 139.14 270 top
CL18  470P_0402_50V7K  [C_0402]  204.76 132.67 270 top
CL19  0.1U_0201_10V6K  [C_0201]  206.84 132.67 270 top
CL20  0.47U_0201_25V6M  [C_0201]  189.6 139.2 270 top
CL21  0.47U_0201_25V6M  [C_0201]  190.95 139.21 270 top
CL22  10P_1808_3KV8J  [C_1808]  174.45 143.82 90 top
CL28  22U_0603_6.3V6M  [C_0603]  182.84 123.25 270 bottom
CL199  1U_0201_10V6M  [C_0201]  205.8 132.67 270 top
CL280  0.1U_0201_10V6K  [C_0201]  182.77 124.27 0 bottom
CLIP1  -  [YDM_DH792_1P-T]  22.77 23.85 180 bottom
CLIP2  -  [YDM_DH792_1P-T]  190.63 46.92 0 top
CMOS1  SHORT PADS~D  [SHORTPADS-NPM]  164.48 18.37 0 bottom
CN1  10U_0402_6.3V6M  [C_0402]  341.13 29.9 180 bottom
CN2  0.1U_0201_25V6K  [C_0201]  340.3 25.98 180 bottom
CN65  0.22U_0201_6.3V6K  [C_0201]  72.21 46.87 0 bottom
CN66  0.22U_0201_6.3V6K  [C_0201]  72.21 45.98 0 bottom
CN67  0.22U_0201_6.3V6K  [C_0201]  72.21 43.88 0 bottom
CN68  0.22U_0201_6.3V6K  [C_0201]  72.21 42.99 0 bottom
CN69  0.22U_0201_6.3V6K  [C_0201]  73.21 40.93 0 bottom
CN70  0.22U_0201_6.3V6K  [C_0201]  73.21 40.04 0 bottom
CN71  0.22U_0201_6.3V6K  [C_0201]  73.24 37.88 0 bottom
CN72  0.22U_0201_6.3V6K  [C_0201]  73.24 36.99 0 bottom
CN174  10U_0402_6.3V6M  [C_0402]  89.19 30.68 270 bottom
CN175  0.01U_0402_16V7K  [C_0402]  87.33 30.67 270 bottom
CN176  0.01U_0402_16V7K  [C_0402]  88.23 30.67 270 bottom
CN177  0.1U_0201_10V6K  [C_0201]  72.81 48.29 180 bottom
CN178  10U_0402_6.3V6M  [C_0402]  86.41 30.67 270 bottom
CN180  0.22U_0201_6.3V6K  [C_0201]  358.57 12.6 270 bottom
CN181  0.22U_0201_6.3V6K  [C_0201]  357.7 12.6 270 bottom
CN182  0.22U_0201_6.3V6K  [C_0201]  356.82 12.59 270 bottom
CN183  0.22U_0201_6.3V6K  [C_0201]  355.93 12.59 270 bottom
CN184  0.22U_0201_6.3V6K  [C_0201]  353.67 12.62 270 bottom
CN185  0.22U_0201_6.3V6K  [C_0201]  352.78 12.62 270 bottom
CN186  0.22U_0201_6.3V6K  [C_0201]  351.62 12.22 270 bottom
CN187  0.22U_0201_6.3V6K  [C_0201]  350.73 12.22 270 bottom
CN188  10U_0402_6.3V6M  [C_0402]  365.72 9.37 90 top
CN189  10U_0402_6.3V6M  [C_0402]  364.8 9.37 90 top
CN190  0.01U_0402_16V7K  [C_0402]  363.89 9.37 90 top
CN191  0.01U_0402_16V7K  [C_0402]  366.63 9.37 90 top
CN192  0.1U_0201_10V6K  [C_0201]  346.67 10.39 90 top
CN193  330U_D2E_6.3VM_R25M  [C_D2E]  340.51 12.91 90 bottom
CN194  0.22U_0201_6.3V6K  [C_0201]  79.49 21.89 180 top
CN195  0.22U_0201_6.3V6K  [C_0201]  79.49 21 180 top
CN196  0.22U_0201_6.3V6K  [C_0201]  79.49 18.86 180 top
CN197  0.22U_0201_6.3V6K  [C_0201]  79.49 17.97 180 top
CN198  0.22U_0201_6.3V6K  [C_0201]  79.47 15.8 180 top
CN199  0.22U_0201_6.3V6K  [C_0201]  79.47 14.91 180 top
CN200  0.22U_0201_6.3V6K  [C_0201]  79.47 12.87 180 top
CN201  0.22U_0201_6.3V6K  [C_0201]  79.47 11.98 180 top
CN202  10U_0402_6.3V6M  [C_0402]  86.5 21.01 0 bottom
CN203  0.01U_0402_16V7K  [C_0402]  86.5 20.12 0 bottom
CN204  0.01U_0402_16V7K  [C_0402]  86.43 6.7 0 bottom
CN205  0.1U_0201_10V6K  [C_0201]  85.8 6.19 90 top
CN206  10U_0402_6.3V6M  [C_0402]  86.43 5.81 0 bottom
CN207  330U_D2E_6.3VM_R25M  [C_D2E]  85.46 21.47 270 top
CN276  0.1U_0201_10V6K  [C_0201]  90.29 43.82 270 bottom
CN277  0.01U_0402_16V7K  [C_0402]  88.65 43.32 270 bottom
CN279  0.01U_0402_16V7K  [C_0402]  89.54 43.33 270 bottom
CN280  0.1U_0201_10V6K  [C_0201]  86.04 43.39 270 bottom
CN281  10U_0402_6.3V6M  [C_0402]  86.81 43.29 270 bottom
CN282  0.01U_0402_16V7K  [C_0402]  87.71 43.33 270 bottom
CN283  0.1U_0201_10V6K  [C_0201]  369.22 9.37 90 top
CN285  0.01U_0402_16V7K  [C_0402]  367.54 9.36 90 top
CN286  0.01U_0402_16V7K  [C_0402]  368.44 9.34 90 top
CN287  0.1U_0201_10V6K  [C_0201]  351.68 11.49 90 top
CN288  0.01U_0402_16V7K  [C_0402]  352.43 11.41 90 top
CN289  10U_0402_6.3V6M  [C_0402]  353.35 11.41 90 top
CN295  0.1U_0201_10V6K  [C_0201]  84.36 24.45 90 top
CN297  0.01U_0402_16V7K  [C_0402]  86.1 24.26 90 top
CN298  0.01U_0402_16V7K  [C_0402]  85.14 24.26 90 top
CN299  0.1U_0201_10V6K  [C_0201]  86.23 16.99 0 bottom
CN300  10U_0402_6.3V6M  [C_0402]  86.3 17.75 0 bottom
CN301  0.01U_0402_16V7K  [C_0402]  86.26 18.65 0 bottom
CR200  5P_0402_50V8C  [C_0402]  15.1 17.98 270 bottom
CR203  0.22U_0201_6.3V6K  [C_0201]  24.15 8.62 90 bottom
CR204  0.22U_0201_6.3V6K  [C_0201]  18.78 8.66 90 bottom
CR205  0.22U_0201_6.3V6K  [C_0201]  23.26 8.62 90 bottom
CR206  0.22U_0201_6.3V6K  [C_0201]  17.84 8.66 90 bottom
CR214  0.1U_0201_25V6K  [C_0201]  34.29 15.51 90 bottom
CR215  10U_0402_6.3V6M  [C_0402]  34.15 18.38 90 bottom
CR217  0.1U_0201_10V6K  [C_0201]  28.37 16.45 0 bottom
CR218  22U_0603_6.3V6M  [C_0603]  27.77 17.38 0 bottom
CR219  100P_0402_50V8J  [C_0402]  20.6 7.92 180 bottom
CR220  1U_0201_6.3V6M  [C_0201]  20.48 9.52 180 bottom
CR221  0.1U_0201_10V6K  [C_0201]  19.89 8.66 0 bottom
CR222  0.1U_0201_10V6K  [C_0201]  17.04 13 270 bottom
CR223  4.7U_0402_6.3V6M  [C_0402]  16.14 12.13 90 bottom
CR224  0.1U_0201_25V6K  [C_0201]  34.12 18.95 90 top
CR225  4.7U_0402_6.3V6M  [C_0402]  34.28 22.51 270 top
CR227  0.1U_0201_25V6K  [C_0201]  10.07 19.76 0 bottom
CR228  4.7U_0402_6.3V6M  [C_0402]  9.9 20.79 0 bottom
CR229  1U_0201_6.3V6M  [C_0201]  16.5 9.84 90 bottom
CR230  0.1U_0201_10V6K  [C_0201]  17.09 10.43 270 bottom
CR234  0.1U_0201_10V6K  [C_0201]  15.65 14.4 90 bottom
CR235  10U_0402_6.3V6M  [C_0402]  16.39 14.12 90 bottom
CR236  0.1U_0201_25V6K  [C_0201]  11.18 25.9 270 bottom
CR237  100P_0402_50V8J  [C_0402]  26.41 8.46 180 bottom
CR238  1U_0201_6.3V6M  [C_0201]  26.22 10.14 180 bottom
CR239  0.1U_0201_10V6K  [C_0201]  25.63 9.4 0 bottom
CR240  100P_0402_50V8J  [C_0402]  23.07 22.69 270 bottom
CR241  1U_0201_6.3V6M  [C_0201]  23.39 21.07 180 bottom
CR242  0.1U_0201_10V6K  [C_0201]  22.83 20.48 0 bottom
CR244  1U_0201_10V6M  [C_0201]  16.85 18.04 270 bottom
CR245  1U_0201_10V6M  [C_0201]  29.14 9 90 bottom
CR246  0.1U_0201_25V6K  [C_0201]  28.25 9 90 bottom
CR247  0.1U_0201_10V6K  [C_0201]  28.13 13.27 0 bottom
CR248  4.7U_0402_6.3V6M  [C_0402]  29.02 12.42 180 bottom
CR249  100P_0402_50V8J  [C_0402]  21.44 8.4 0 bottom
CR250  1U_0201_6.3V6M  [C_0201]  21.65 9.16 0 bottom
CR251  0.1U_0201_10V6K  [C_0201]  25.94 7.67 0 bottom
CR252  100P_0402_50V8J  [C_0402]  20.98 22.42 0 bottom
CR253  1U_0201_6.3V6M  [C_0201]  21.1 21.09 0 bottom
CR254  0.1U_0201_10V6K  [C_0201]  21.69 21.68 180 bottom
CR255  1U_0201_10V6M  [C_0201]  7.04 18.56 180 bottom
CR256  0.1U_0201_25V6K  [C_0201]  8.98 21.62 90 bottom
CT1  0.1U_0201_10V6K  [C_0201]  38.35 46.11 180 top
CT2  0.22U_0201_6.3V6K  [C_0201]  37.73 31.44 270 bottom
